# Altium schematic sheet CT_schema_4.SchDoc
size 297 x 271 mm
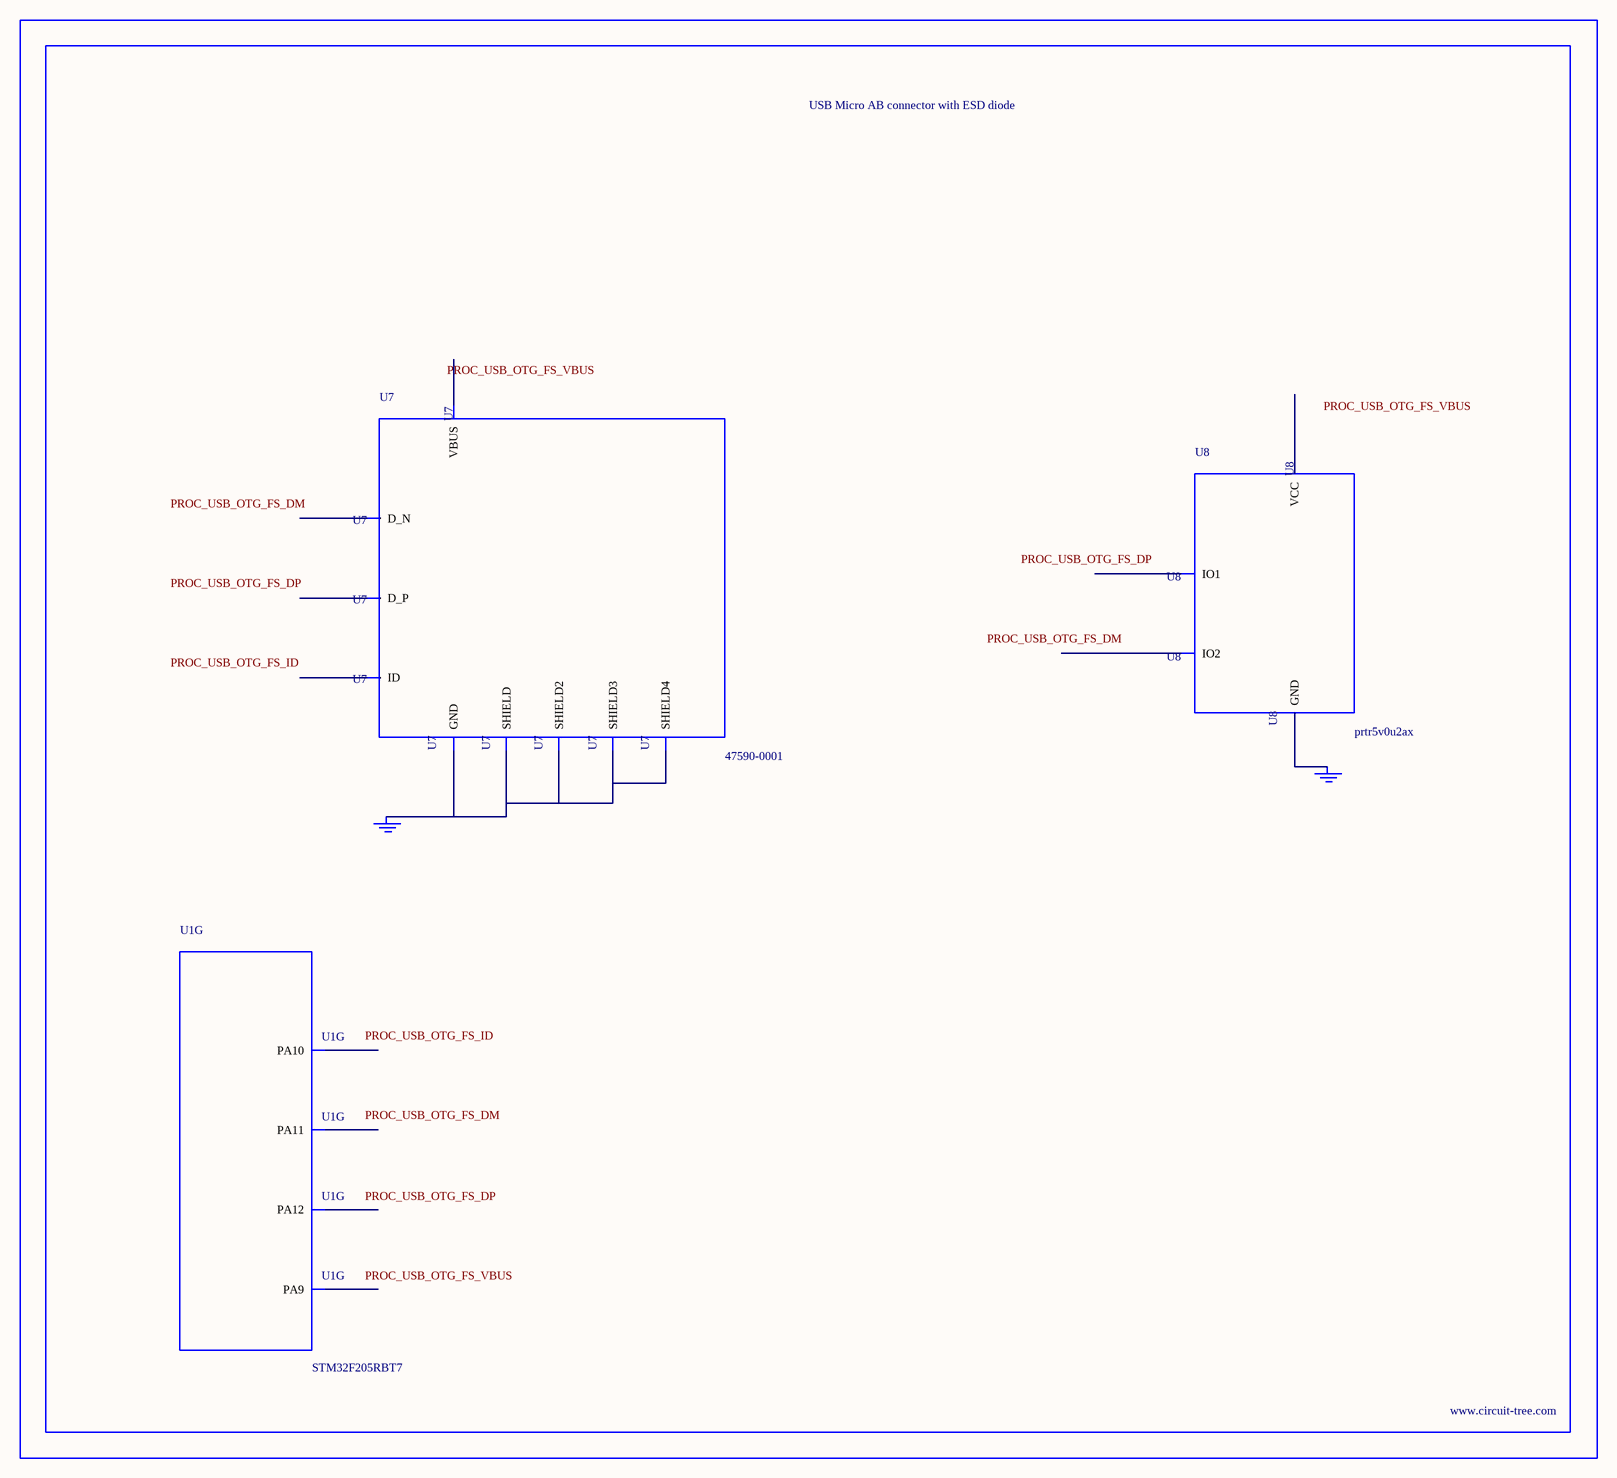
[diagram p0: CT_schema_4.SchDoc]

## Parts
BORDER3  (no value)
GND_INSTANCE_3_0  (no value)
GND_INSTANCE_3_1  (no value)
U1  STM32F205RBT7  [LQFP64]  (part G of 7)
U7  47590-0001  [MICRO_USB_AB]
U8  prtr5v0u2ax  [SOT143B]

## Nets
NetGND_INSTANCE_3_0_0: GND_INSTANCE_3_0.0(GND) U7.5(GND) U7.6(SHIELD) U7.7(SHIELD2) U7.8(SHIELD3) U7.9(SHIELD4)
NetGND_INSTANCE_3_1_0: GND_INSTANCE_3_1.0(GND) U8.1(GND)

Not connected (* = marked no-connect by the designer): U1 42(PA9) 43(PA10) 44(PA11) 45(PA12); U7 1(VBUS) 2(D_N) 3(D_P) 4(ID); U8 2(IO1) 3(IO2) 4(VCC)

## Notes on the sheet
- Labels drawn without touching a wire or pin: PROC_USB_OTG_FS_DM, PROC_USB_OTG_FS_DP, PROC_USB_OTG_FS_ID, PROC_USB_OTG_FS_VBUS

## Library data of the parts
BORDER3 = BORDER_PAGE3
GND_INSTANCE_3_0 GND_INSTANCE_3_1 = GND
